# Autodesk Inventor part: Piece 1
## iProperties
Created: 2006-10
Part Number: Piece 1
Document SubType Name: Modeling
Designer: Lab User
Author: Lab User
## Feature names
1. Extrusion1
2. Extrusion2
3. Hole1
4. Hole3
5. Hole4
6. Extrusion4
7. Hole5
8. Hole6
9. Hole7
